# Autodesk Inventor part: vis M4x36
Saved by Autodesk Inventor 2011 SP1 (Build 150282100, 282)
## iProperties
Created: 2010-12
Part Number: vis M4x36
Document SubType Name: Modeling
Designer: eric
Density: 1 g/cm^3
Author: eric
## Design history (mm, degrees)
feature "Base1"
node "Solide1"
node "Corps solides"
node "Corps surfaciques"
